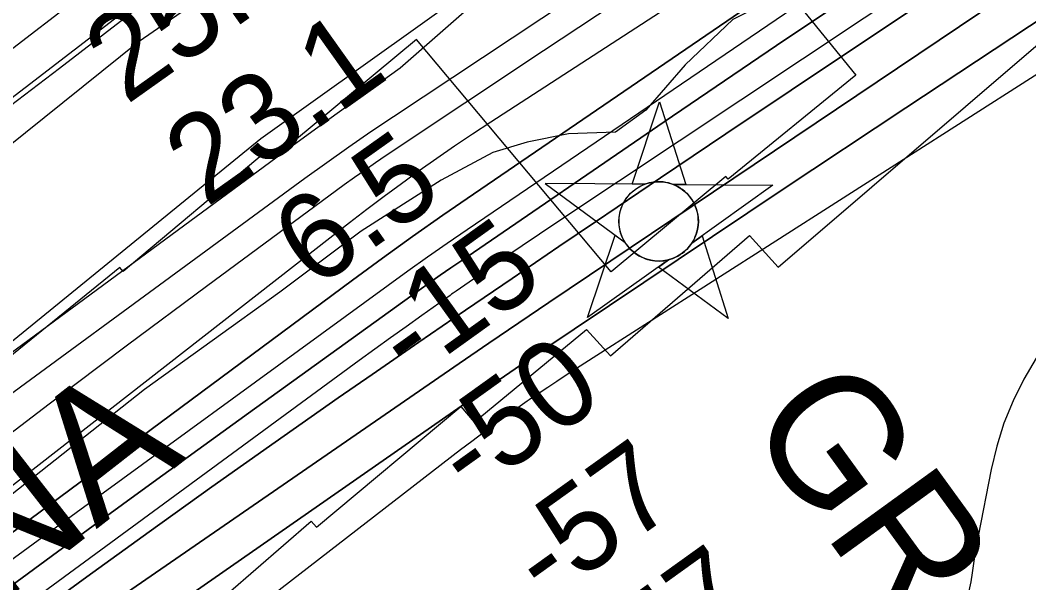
# Model space of a CAD drawing. Extents: x 3477039 to 3515015, y 546746 to 572297.
# Drawn here: x 3485493 to 3486269, y 561273 to 561707 of the extents above; entities that cross this region are included whole.
import ezdxf

# ---------------------------------------------------------------- set-up
doc = ezdxf.new("R2010")
doc.units = 0
for name, color, linetype in [('V-CHAN-NAID', 7, 'Continuous'), ('V-FLOD-BASE', 7, 'Continuous'), ('V-LEVE-TOET', 7, 'Continuous'), ('V-RIVR-EDGE', 7, 'Continuous'), ('V-RIVR-RANG', 7, 'Continuous'), ('V-RRAP-FSHR', 7, 'Continuous'), ('V-RRAP-RVMT', 7, 'Continuous'), ('V-RRAP-RVMT-IDEN', 7, 'Continuous'), ('V-SURV-LINE', 7, 'Continuous'), ('V-TOPO-DPTH', 7, 'Continuous'), ('V-TOPO-MAJR', 7, 'Continuous'), ('V-TOPO-MINR', 7, 'Continuous'), ('V-TOPO-WATR', 7, 'Continuous')]:
    doc.layers.add(name, color=color, linetype=linetype)

msp = doc.modelspace()

# ---------------------------------------------------------------- linework, layer by layer
at = {"layer": 'V-CHAN-NAID'}
for points in [[(3485973.21, 561580.28), (3485963.62, 561580.35), (3485984.74, 561643.83), (3486004.97, 561580.06), (3485995.38, 561580.12), (3485993.8, 561580.7), (3485991.71, 561581.32), (3485989.67, 561581.77), (3485987.63, 561582.08), (3485986.47, 561582.19), (3485984.93, 561582.28), (3485983.21, 561582.27), (3485981.84, 561582.2), (3485979.93, 561582), (3485978.57, 561581.78), (3485976.78, 561581.4), (3485975.25, 561580.98), (3485974.22, 561580.65)], [(3485973.21, 561580.28), (3485896.71, 561580.82), (3485958.28, 561535.42), (3485957.17, 561537.33), (3485956.36, 561538.96), (3485955.53, 561540.93), (3485954.83, 561542.98), (3485954.47, 561544.31), (3485954.11, 561545.93), (3485953.87, 561547.38), (3485953.68, 561548.97), (3485953.57, 561550.71), (3485953.56, 561552.29), (3485953.66, 561554.36), (3485953.85, 561555.98), (3485954.24, 561558.19), (3485954.72, 561560.11), (3485955.32, 561562), (3485955.98, 561563.68), (3485956.7, 561565.26), (3485957.52, 561566.8), (3485958.58, 561568.54), (3485959.61, 561570.01), (3485960.61, 561571.27), (3485961.61, 561572.42), (3485962.92, 561573.76), (3485963.97, 561574.72), (3485965.69, 561576.12), (3485966.9, 561576.99), (3485968.59, 561578.06), (3485970.32, 561579), (3485971.77, 561579.69)], [(3485995.38, 561580.12), (3486071.87, 561579.58), (3486009.67, 561535.06), (3486010.58, 561536.55), (3486011.56, 561538.39), (3486012.27, 561539.98), (3486013.01, 561541.93), (3486013.56, 561543.72), (3486013.96, 561545.36), (3486014.32, 561547.37), (3486014.5, 561548.94), (3486014.63, 561551.15), (3486014.6, 561553.21), (3486014.41, 561555.43), (3486014.14, 561557.19), (3486013.65, 561559.42), (3486013.01, 561561.56), (3486012.26, 561563.54), (3486011.61, 561564.98), (3486010.61, 561566.9), (3486009.54, 561568.62), (3486008.33, 561570.32), (3486007.07, 561571.86), (3486005.8, 561573.23), (3486004.17, 561574.76), (3486002.42, 561576.17), (3486000.74, 561577.35), (3485998.85, 561578.48), (3485997.38, 561579.24)], [(3485991.64, 561522.15), (3485929.44, 561477.63), (3485950.56, 561541.11), (3485958.28, 561535.42), (3485958.91, 561534.46), (3485960.3, 561532.6), (3485961.51, 561531.18), (3485962.98, 561529.68), (3485964.37, 561528.43), (3485965.82, 561527.27), (3485967.22, 561526.29), (3485968.9, 561525.25), (3485970.61, 561524.34), (3485972.41, 561523.53), (3485973.85, 561522.97), (3485975.48, 561522.44), (3485977.71, 561521.88), (3485979.24, 561521.59), (3485981.26, 561521.34), (3485982.8, 561521.23), (3485984.66, 561521.21), (3485986.35, 561521.29), (3485988.06, 561521.46), (3485989.96, 561521.78)], [(3486009.67, 561535.06), (3486017.47, 561540.64), (3486037.69, 561476.86), (3485983.84, 561516.57), (3485991.64, 561522.15), (3485993.31, 561522.63), (3485994.92, 561523.19), (3485997.08, 561524.1), (3485998.81, 561524.99), (3486000.68, 561526.1), (3486002.42, 561527.31), (3486003.97, 561528.56), (3486005.25, 561529.72), (3486006.64, 561531.15), (3486007.84, 561532.55), (3486008.96, 561534.02)]]:
    msp.add_lwpolyline(points, close=True, dxfattribs=at)
msp.add_circle((3485984.09, 561551.75), 30.54, dxfattribs=at)
at = {"layer": 'V-FLOD-BASE'}
msp.add_lwpolyline([(3485679.25, 561787.91), (3485642.6, 561761.97), (3485523.12, 561669.62), (3485398.91, 561574.98), (3485252.77, 561459.51), (3485106.66, 561346.38), (3484987.18, 561254.61), (3484829.85, 561134.58), (3484677.25, 561018.01), (3484564.29, 560932.61)], dxfattribs=at)
at = {"layer": 'V-LEVE-TOET'}
msp.add_lwpolyline([(3485482.53, 561608.56), (3485584.32, 561690.58), (3485656.42, 561740.71), (3485685.36, 561759.7), (3485697.76, 561767.17), (3485746.28, 561806.45), (3485764.6, 561819.12), (3485790.58, 561835.22), (3485830.66, 561854.09), (3485837.7, 561854.59), (3485851.72, 561850.91), (3485860.54, 561853.15), (3485864.69, 561857.2), (3485865.33, 561861.88), (3485864.83, 561868.92), (3485885.67, 561896.22), (3485897.62, 561915.42), (3485914.86, 561935.72), (3485972.91, 561987.19), (3486075.24, 562066.27), (3486184.63, 562147.02), (3486302.32, 562235.87)], dxfattribs=at)
at = {"layer": 'V-RIVR-EDGE'}
msp.add_lwpolyline([(3486658.66, 562131.52), (3486602.82, 562099.18), (3486581.31, 562071.05), (3486492.93, 562014.29), (3486429.12, 561977.07), (3486376.99, 561958.82), (3486275.08, 561877.58), (3486203.84, 561814.03), (3486127.11, 561756.62), (3486092.11, 561724.23), (3486071.27, 561722.45), (3486041.21, 561707.2), (3486004.36, 561672.37), (3485974.25, 561637.52), (3485950.92, 561620.42), (3485914.77, 561619.28), (3485882.89, 561612.62), (3485856.52, 561604.72), (3485816.64, 561583.37), (3485755.27, 561544.31), (3485692.66, 561497.29), (3485588.31, 561422.18), (3485411.5, 561282.3)], dxfattribs=at)
at = {"layer": 'V-RRAP-FSHR'}
msp.add_lwpolyline([(3484364.21, 560616.5), (3484735.59, 560876.45), (3485089.42, 561146.25), (3485314.79, 561319.6), (3485677.84, 561615.5), (3485963.36, 561819.75), (3486251.23, 561993.04), (3487197.2, 562666.32), (3487589.28, 562882.19)], dxfattribs=at)
at = {"layer": 'V-RRAP-RVMT'}
for points in [[(3486272.41, 561971.58), (3486262.41, 561982.93), (3486152.27, 561893.14), (3486149.36, 561896.46), (3486028.2, 561796.81), (3486135.83, 561664.4), (3486037.61, 561584.32), (3486035.7, 561586.32), (3485947.63, 561512.95), (3485797.7, 561691.77), (3485687.2, 561600.03), (3485682.18, 561605.5), (3485572.01, 561513.24), (3485569.36, 561516.11), (3485453.32, 561421.95)], [(3485476.6, 561150.27), (3485591.73, 561249.45), (3485610.3, 561228.48), (3485716.77, 561320.76), (3485720.83, 561316.07), (3485831.95, 561409.07), (3485842.1, 561396.98), (3485928.56, 561468.55), (3485947.06, 561448.26), (3486054.03, 561540.96), (3486076.15, 561516.35), (3486292.38, 561702.21), (3486300.62, 561692.69), (3486412.29, 561782.71), (3486435.96, 561754.49), (3486544.86, 561844.89), (3486636.41, 561735.78), (3486747.94, 561828.87), (3486787.8, 561781.37), (3486900.76, 561873.94)]]:
    msp.add_lwpolyline(points, dxfattribs=at)
at = {"layer": 'V-SURV-LINE'}
for points in [[(3483524.96, 560175.56), (3487277.1, 563062.76)], [(3487295.39, 563038.98), (3483543.26, 560151.78)]]:
    msp.add_lwpolyline(points, dxfattribs=at)
at = {"layer": 'V-TOPO-DPTH'}
for points in [[(3487351.17, 562549.43), (3486662.89, 562123.48), (3486647.65, 562114.01), (3486632.42, 562104.52), (3486617.22, 562094.98), (3486602.04, 562085.41), (3486577.27, 562069.75), (3486574.5, 562067.98), (3486571.72, 562066.22), (3486568.96, 562064.44), (3486566.2, 562062.65), (3486489.42, 562012.84), (3486448.37, 561985.99), (3486407.45, 561958.95), (3486366.73, 561931.61), (3486326.14, 561904.08), (3485841.57, 561572.81), (3485818.08, 561556.55), (3485794.72, 561540.1), (3485771.55, 561523.39), (3485748.51, 561506.49), (3485235.84, 561125.81)], [(3485235.84, 561125.81), (3485748.51, 561506.49), (3485771.55, 561523.39), (3485794.72, 561540.1), (3485818.08, 561556.55), (3485841.57, 561572.81), (3486326.14, 561904.08), (3486366.73, 561931.61), (3486407.45, 561958.95), (3486448.37, 561985.99), (3486489.42, 562012.84), (3486566.2, 562062.65), (3486568.96, 562064.44), (3486571.72, 562066.22), (3486574.5, 562067.98), (3486577.27, 562069.75), (3486602.04, 562085.41), (3486617.22, 562094.98), (3486632.42, 562104.52), (3486647.65, 562114.01), (3486662.89, 562123.48), (3487351.17, 562549.43)], [(3487384.05, 562458.33), (3486673.72, 562008.45), (3486666.57, 562003.91), (3486659.42, 561999.37), (3486652.29, 561994.81), (3486645.15, 561990.25), (3486633.34, 561982.68), (3486629.69, 561980.31), (3486628.48, 561979.51), (3486602.92, 561962.58), (3486588.95, 561953.3), (3486574.99, 561944), (3486561.05, 561934.66), (3486547.12, 561925.3), (3485899.58, 561489.16), (3485876.5, 561473.56), (3485853.45, 561457.9), (3485830.45, 561442.17), (3485807.49, 561426.39), (3485352.95, 561112.91)], [(3485352.95, 561112.91), (3485807.49, 561426.39), (3485830.45, 561442.17), (3485853.45, 561457.9), (3485876.5, 561473.56), (3485899.58, 561489.16), (3486547.12, 561925.3), (3486561.05, 561934.66), (3486574.99, 561944), (3486588.95, 561953.3), (3486602.92, 561962.58), (3486628.48, 561979.51), (3486629.69, 561980.31), (3486633.34, 561982.68), (3486645.15, 561990.25), (3486652.29, 561994.81), (3486659.42, 561999.37), (3486666.57, 562003.91), (3486673.72, 562008.45), (3487384.05, 562458.33)], [(3487063.14, 562325.95), (3486650.17, 562065.51), (3486623.12, 562048.35), (3486596.12, 562031.11), (3486569.22, 562013.73), (3486542.37, 561996.25), (3486335.62, 561860.96), (3486248.38, 561803.48), (3486161.38, 561745.62), (3486074.75, 561687.22), (3485988.37, 561628.45), (3485832.5, 561521.69), (3485824.26, 561516), (3485816.04, 561510.27), (3485807.86, 561504.48), (3485799.71, 561498.65), (3485668.57, 561404.12), (3485595, 561350.82), (3485521.61, 561297.29), (3485448.46, 561243.42)], [(3485448.46, 561243.42), (3485521.61, 561297.29), (3485595, 561350.82), (3485668.57, 561404.12), (3485799.71, 561498.65), (3485807.86, 561504.48), (3485816.04, 561510.27), (3485824.26, 561516), (3485832.5, 561521.69), (3485988.37, 561628.45), (3486074.75, 561687.22), (3486161.38, 561745.62), (3486248.38, 561803.48), (3486335.62, 561860.96), (3486542.37, 561996.25), (3486569.22, 562013.73), (3486596.12, 562031.11), (3486623.12, 562048.35), (3486650.17, 562065.51), (3487063.14, 562325.95)], [(3486893.68, 562326.24), (3486590.04, 562133.25), (3486567.54, 562118.92), (3486545.06, 562104.57), (3486522.6, 562090.18), (3486500.15, 562075.76), (3486171.6, 561864.29), (3486102.28, 561819.42), (3486033.1, 561774.32), (3485964.16, 561728.87), (3485895.37, 561683.18), (3485774.41, 561602.39), (3485766.26, 561596.86), (3485758.16, 561591.26), (3485750.14, 561585.55), (3485742.17, 561579.76), (3485636.15, 561501.65), (3485575.42, 561456.48), (3485514.96, 561410.95), (3485454.91, 561364.88)], [(3487172.02, 562280.69), (3486707.52, 561985.48), (3486679.91, 561967.9), (3486652.33, 561950.28), (3486624.78, 561932.6), (3486597.26, 561914.88), (3486460.53, 561826.69), (3486364.82, 561764.6), (3486269.33, 561702.17), (3486174.18, 561639.25), (3486079.24, 561575.99), (3485892.73, 561451), (3485881.14, 561443.18), (3485869.58, 561435.33), (3485858.06, 561427.42), (3485846.57, 561419.46), (3485436.22, 561133.74)], [(3485436.22, 561133.74), (3485846.57, 561419.46), (3485858.06, 561427.42), (3485869.58, 561435.33), (3485881.14, 561443.18), (3485892.73, 561451), (3486079.24, 561575.99), (3486174.18, 561639.25), (3486269.33, 561702.17), (3486364.82, 561764.6), (3486460.53, 561826.69), (3486597.26, 561914.88), (3486624.78, 561932.6), (3486652.33, 561950.28), (3486679.91, 561967.9), (3486707.52, 561985.48), (3487172.02, 562280.69)], [(3484980.84, 560866.3), (3485543.99, 561277.8), (3485592.1, 561312.68), (3485640.36, 561347.33), (3485688.88, 561381.63), (3485737.57, 561415.69), (3485763.72, 561433.86), (3485799.49, 561458.6), (3485835.32, 561483.27), (3485871.23, 561507.82), (3485907.2, 561532.28), (3485935.39, 561551.38), (3485985.53, 561585.27), (3486035.72, 561619.09), (3486085.99, 561652.78), (3486136.32, 561686.4), (3486587.8, 561987.23), (3486601.1, 561996.04), (3486614.43, 562004.79), (3486627.81, 562013.47), (3486641.22, 562022.09), (3486768.8, 562103.61), (3486845.98, 562153.03), (3486923.1, 562202.55)], [(3484980.84, 560866.3), (3485543.99, 561277.8), (3485592.1, 561312.68), (3485640.36, 561347.33), (3485688.88, 561381.63), (3485737.57, 561415.69), (3485763.72, 561433.86), (3485799.49, 561458.6), (3485835.32, 561483.27), (3485871.23, 561507.82), (3485907.2, 561532.28), (3485935.39, 561551.38), (3485985.53, 561585.27), (3486035.72, 561619.09), (3486085.99, 561652.78), (3486136.32, 561686.4), (3486587.8, 561987.23), (3486601.1, 561996.04), (3486614.43, 562004.79), (3486627.81, 562013.47), (3486641.22, 562022.09), (3486768.8, 562103.61), (3486845.98, 562153.03), (3486923.1, 562202.55)]]:
    msp.add_lwpolyline(points, dxfattribs=at)
at = {"layer": 'V-TOPO-MAJR'}
msp.add_lwpolyline([(3486888.21, 562058.58), (3486816.69, 562012.25), (3486733.59, 561958.72), (3486703.5, 561939.35), (3486673.39, 561920), (3486643.26, 561900.68), (3486613.12, 561881.37), (3485927.19, 561442.4), (3485920.04, 561437.8), (3485912.91, 561433.17), (3485905.8, 561428.51), (3485898.7, 561423.81), (3485886.29, 561415.55), (3485884.55, 561414.38), (3485883.69, 561413.78), (3485882.84, 561413.18), (3485866.67, 561401.73), (3485857.78, 561395.34), (3485848.94, 561388.87), (3485840.19, 561382.3), (3485831.49, 561375.65), (3485040.85, 560763.41)], dxfattribs=at)
at = {"layer": 'V-TOPO-MINR'}
for points in [[(3486937.3, 562648.12), (3486849.98, 562579.64), (3486763.3, 562510.35), (3486677.06, 562440.52), (3486467.47, 562269.2), (3486455.76, 562259.54), (3486444.1, 562249.82), (3486432.52, 562240), (3486421, 562230.11), (3486347.23, 562166.25), (3486328.68, 562149.58), (3486310.57, 562132.47), (3486293.11, 562114.7), (3485785.08, 561669.83), (3485757.68, 561650.07), (3485730.32, 561630.24), (3485703.03, 561610.31), (3485675.8, 561590.32), (3484917.21, 561031.26)], [(3487233.69, 562571.95), (3486596.77, 562166.82), (3486563.84, 562145.87), (3486530.91, 562124.91), (3486497.99, 562103.94), (3486465.07, 562082.97), (3486416.84, 562052.24), (3486359.92, 562015.74), (3486303.13, 561979.02), (3486246.55, 561941.98), (3486190.11, 561904.72), (3485779.95, 561632.27), (3485762.71, 561620.64), (3485745.59, 561608.86), (3485728.63, 561596.83), (3485711.78, 561584.65), (3485388.52, 561347.4)], [(3487254.9, 562464.63), (3486655.86, 562091.81), (3486620.33, 562069.6), (3486584.86, 562047.3), (3486549.49, 562024.85), (3486514.17, 562002.31), (3486497.87, 561991.86), (3486454.56, 561963.85), (3486411.41, 561935.6), (3486368.5, 561906.99), (3486325.74, 561878.15), (3485836.74, 561545.27), (3485821.42, 561534.73), (3485806.16, 561524.08), (3485791.01, 561513.29), (3485775.93, 561502.4), (3485502.7, 561303.05), (3485407.67, 561233.39)], [(3487384.05, 562458.33), (3486673.72, 562008.45), (3486666.57, 562003.91), (3486659.42, 561999.37), (3486652.29, 561994.81), (3486645.15, 561990.25), (3486633.34, 561982.68), (3486629.69, 561980.31), (3486628.48, 561979.51), (3486602.92, 561962.58), (3486588.95, 561953.3), (3486574.99, 561944), (3486561.05, 561934.66), (3486547.12, 561925.3), (3485899.58, 561489.16), (3485876.5, 561473.56), (3485853.45, 561457.9), (3485830.45, 561442.17), (3485807.49, 561426.39), (3485352.95, 561112.91)], [(3487063.14, 562325.95), (3486650.17, 562065.51), (3486623.12, 562048.35), (3486596.12, 562031.11), (3486569.22, 562013.73), (3486542.37, 561996.25), (3486335.62, 561860.96), (3486248.38, 561803.48), (3486161.38, 561745.62), (3486074.75, 561687.22), (3485988.37, 561628.45), (3485832.5, 561521.69), (3485824.26, 561516), (3485816.04, 561510.27), (3485807.86, 561504.48), (3485799.71, 561498.65), (3485668.57, 561404.12), (3485595, 561350.82), (3485521.61, 561297.29), (3485448.46, 561243.42)], [(3486893.68, 562326.24), (3486590.04, 562133.25), (3486567.54, 562118.92), (3486545.06, 562104.57), (3486522.6, 562090.18), (3486500.15, 562075.76), (3486171.6, 561864.29), (3486102.28, 561819.42), (3486033.1, 561774.32), (3485964.16, 561728.87), (3485895.37, 561683.18), (3485774.41, 561602.39), (3485766.26, 561596.86), (3485758.16, 561591.26), (3485750.14, 561585.55), (3485742.17, 561579.76), (3485636.15, 561501.65), (3485575.42, 561456.48), (3485514.96, 561410.95), (3485454.91, 561364.88)], [(3486905.76, 562305.56), (3486836.33, 562261.46), (3486766.9, 562217.37), (3486697.46, 562173.28), (3486583.56, 562100.97), (3486571.08, 562093.02), (3486558.63, 562085.05), (3486546.19, 562077.04), (3486533.78, 562069.01), (3485854.81, 561628.13), (3485840.88, 561618.95), (3485827.04, 561609.65), (3485813.31, 561600.17), (3485799.67, 561590.56), (3485786.16, 561580.78), (3485772.73, 561570.88), (3485759.43, 561560.82), (3485746.21, 561550.64), (3484996.96, 560965.99)], [(3487172.02, 562280.69), (3486707.52, 561985.48), (3486679.91, 561967.9), (3486652.33, 561950.28), (3486624.78, 561932.6), (3486597.26, 561914.88), (3486460.53, 561826.69), (3486364.82, 561764.6), (3486269.33, 561702.17), (3486174.18, 561639.25), (3486079.24, 561575.99), (3485892.73, 561451), (3485881.14, 561443.18), (3485869.58, 561435.33), (3485858.06, 561427.42), (3485846.57, 561419.46), (3485436.22, 561133.74)], [(3486923.1, 562202.55), (3486845.98, 562153.03), (3486768.8, 562103.61), (3486641.22, 562022.09), (3486627.81, 562013.47), (3486614.43, 562004.79), (3486601.1, 561996.04), (3486587.8, 561987.23), (3486136.32, 561686.4), (3486085.99, 561652.78), (3486035.72, 561619.09), (3485985.53, 561585.27), (3485935.39, 561551.38), (3485907.2, 561532.28), (3485871.23, 561507.82), (3485835.32, 561483.27), (3485799.49, 561458.6), (3485763.72, 561433.86), (3485737.57, 561415.69), (3485688.88, 561381.63), (3485640.36, 561347.33), (3485592.1, 561312.68), (3485543.99, 561277.8), (3484980.84, 560866.3)], [(3486869, 562184.73), (3486645.28, 562042.17), (3486625.62, 562029.56), (3486606.02, 562016.88), (3486586.5, 562004.07), (3486567.02, 561991.19), (3485905.73, 561550.8), (3485892.36, 561541.84), (3485879.02, 561532.85), (3485865.71, 561523.79), (3485852.44, 561514.68), (3485828.32, 561498.04), (3485825.95, 561496.4), (3485824.77, 561495.57), (3485823.59, 561494.74), (3485801.76, 561479.22), (3485789.69, 561470.59), (3485777.65, 561461.93), (3485765.64, 561453.21), (3485753.67, 561444.46), (3484982.25, 560877.81)], [(3486274.44, 561446.24), (3486264.98, 561430.16), (3486256.81, 561413.46), (3486249.72, 561396.38), (3486244.25, 561378.7), (3486239.86, 561360.64), (3486229.87, 561309.18), (3486228.58, 561302.18), (3486227.39, 561295.16), (3486226.34, 561288.12), (3486225.39, 561281.07), (3486224.21, 561274.08), (3486222.65, 561267.19)]]:
    msp.add_lwpolyline(points, dxfattribs=at)
at = {"layer": 'V-TOPO-WATR'}
msp.add_lwpolyline([(3487351.17, 562549.43), (3486662.89, 562123.48), (3486647.65, 562114.01), (3486632.42, 562104.52), (3486617.22, 562094.98), (3486602.04, 562085.41), (3486577.27, 562069.75), (3486574.5, 562067.98), (3486571.72, 562066.22), (3486568.96, 562064.44), (3486566.2, 562062.65), (3486489.42, 562012.84), (3486448.37, 561985.99), (3486407.45, 561958.95), (3486366.73, 561931.61), (3486326.14, 561904.08), (3485841.57, 561572.81), (3485818.08, 561556.55), (3485794.72, 561540.1), (3485771.55, 561523.39), (3485748.51, 561506.49), (3485235.84, 561125.81)], dxfattribs=at)

# ---------------------------------------------------------------- texts
at = {"layer": 'V-CHAN-NAID'}
msp.add_text('GRAMERCY INTAKE (146.6)', height=100, rotation=305.96759, dxfattribs=at).set_placement((3486049.42, 561396.15))
at = {"layer": 'V-RIVR-RANG'}
for s, rotation, p in [('25.6', 35.40833, (3485574.37, 561641)), ('23.1', 35.40833, (3485635.95, 561562.08)), ('6.5', 35.40833, (3485719.24, 561498.6)), ('-15', 35.68861, (3485793.39, 561428.22)), ('-50', 35.68861, (3485839.31, 561338.09)), ('-57', 35.68861, (3485897.87, 561257.03)), ('-57', 35.68861, (3485956.01, 561175.66))]:
    msp.add_text(s, height=67, rotation=rotation, dxfattribs=at).set_placement(p)
at = {"layer": 'V-RRAP-RVMT-IDEN'}
msp.add_text('ANGELINA', height=100, rotation=37.9856, dxfattribs=at).set_placement((3485088.53, 560953.12))

doc.saveas('drawing.dxf')
